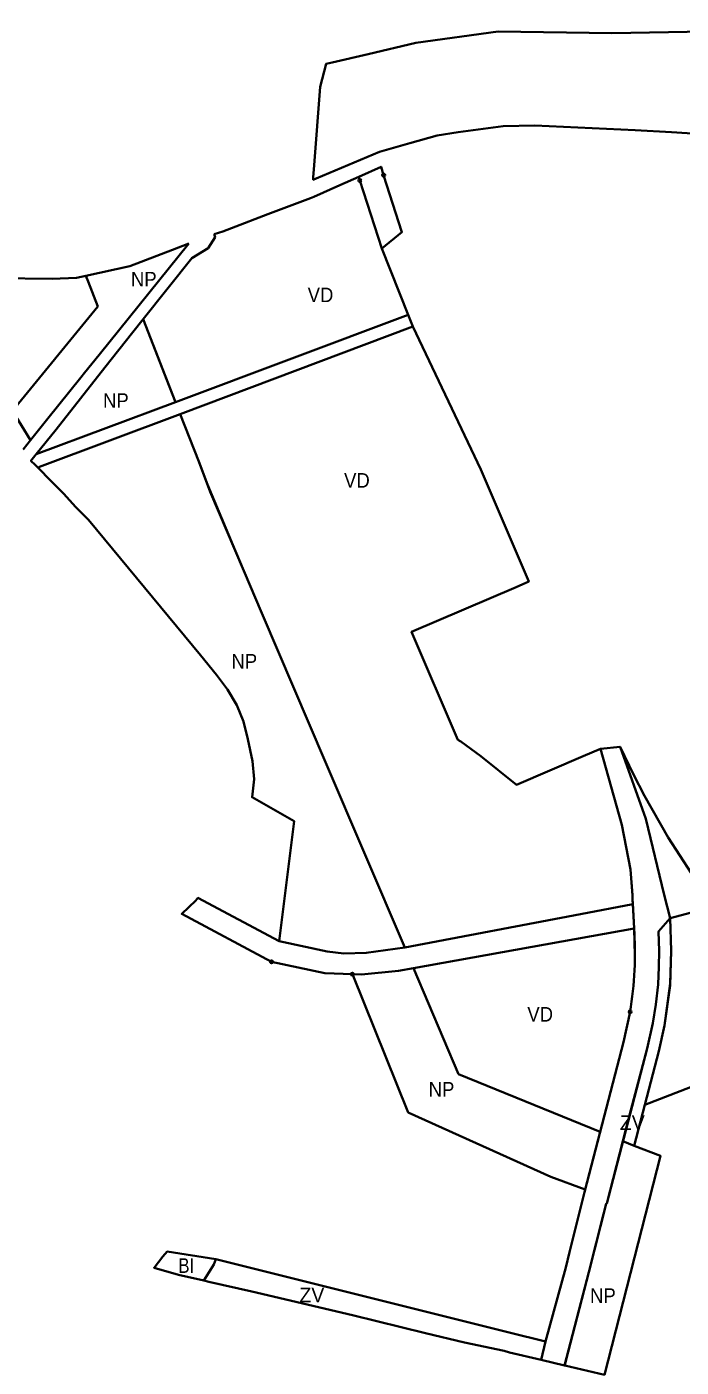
# Model space of a CAD drawing. Extents: x -650276 to -642489, y -1074311 to -1066658.
# Drawn here: x -649558 to -649019, y -1070272 to -1069167 of the extents above; entities that cross this region are included whole.
import ezdxf

# ---------------------------------------------------------------- set-up
doc = ezdxf.new("R2010")
doc.units = 0
doc.header["$LTSCALE"] = 4.8
doc.header["$PDMODE"] = 32
doc.header["$PDSIZE"] = 2.4
for name, color, linetype, lineweight in [('13', 7, 'Continuous', 35), ('15', 7, 'Continuous', 35), ('2', 7, 'Continuous', 35), ('24', 7, 'Continuous', 35), ('35', 7, 'Continuous', 35), ('40', 7, 'Continuous', 35), ('41', 7, 'Continuous', 35), ('48', 7, 'Continuous', 35)]:
    doc.layers.add(name, color=color, linetype=linetype, lineweight=lineweight)
doc.layers.add('62', color=7, linetype='Continuous')

msp = doc.modelspace()

# ---------------------------------------------------------------- linework, layer by layer
at = {"layer": '13'}
msp.add_lwpolyline([(-648800.85, -1069841.52), (-649028.017, -1069902.109), (-649027.135, -1069928.902), (-649027.953, -1069955.702), (-649032.644, -1069990.371), (-649037.411, -1070011.659), (-649048.918, -1070055.852), (-648931.057, -1070010.171)], dxfattribs=at)
at = {"layer": '15'}
msp.add_line((-649057.868, -1069910.51), (-649058.82, -1069890.548), dxfattribs=at)
for points in [[(-649561.17, -1069515.83), (-649555.16, -1069508.07), (-649570.03, -1069483.83), (-649688.625, -1069418.156), (-649755.971, -1069381.179), (-649810.846, -1069362.154), (-649875.434, -1069357.751), (-649934.363, -1069369.537), (-649945.397, -1069375.277), (-649977.239, -1069391.714), (-649994.329, -1069405.451)], [(-649431.761, -1069486.57), (-649240.202, -1069414.528), (-649244.08, -1069404.753), (-649435.578, -1069476.772), (-649550.53, -1069519.68)], [(-649548.881, -1069530.963), (-649547.733, -1069530.185), (-649431.761, -1069486.57)], [(-649550.53, -1069519.68), (-649554.83, -1069525), (-649551.32, -1069528.49), (-649549.69, -1069530.14), (-649548.881, -1069530.963)], [(-649029.61, -1069835.47), (-649049.22, -1069801.23), (-649058.34, -1069783.72), (-649069.4, -1069760.67)], [(-649069.4, -1069760.67), (-649048, -1069820), (-649032.928, -1069882.782)], [(-649032.928, -1069882.782), (-649028.017, -1069902.109), (-648800.85, -1069841.52), (-648806.946, -1069821.79), (-648846.939, -1069832.584), (-648846.94, -1069832.584)], [(-648846.94, -1069832.584), (-648916.03, -1069847.12), (-649010.55, -1069865.09), (-649029.61, -1069835.47)], [(-649417.234, -1069885.193), (-649418.94, -1069887.36), (-649430.515, -1069898.514), (-649356.458, -1069937.945)], [(-649246.81, -1069926.27), (-649278.492, -1069930.573), (-649296.851, -1069931.092), (-649310.738, -1069929.342), (-649350.222, -1069920.873), (-649417.234, -1069885.193)], [(-649058.82, -1069890.548), (-649101.89, -1069898.73), (-649246.81, -1069926.27)], [(-649289.95, -1069948.146), (-649282.437, -1069948.342), (-649251.805, -1069945.276), (-649239.635, -1069943.094), (-649057.868, -1069910.51)], [(-649356.458, -1069937.945), (-649312.646, -1069947.342), (-649289.95, -1069948.146)]]:
    msp.add_lwpolyline(points, dxfattribs=at)
for p in [(-649356.458, -1069937.945), (-649289.95, -1069948.146)]:
    msp.add_point(p, dxfattribs=at)
at = {"layer": '2'}
msp.add_lwpolyline([(-649442.63, -1070176.69), (-649402.29, -1070182.92), (-649404.2, -1070187.43), (-649412.2, -1070200.71), (-649433.3, -1070195.89), (-649453.27, -1070190.02), (-649446.19, -1070180.76)], close=True, dxfattribs=at)
at = {"layer": '24'}
for p, q in [((-649283.702, -1069294.132), (-649265.774, -1069350.068)), ((-649058.858, -1069889.759), (-649057.868, -1069910.51)), ((-649057.134, -1069932.873), (-649057.868, -1069910.51))]:
    msp.add_line(p, q, dxfattribs=at)
for points in [[(-648781.015, -1069167.44), (-649076.02, -1069172.683), (-649169.781, -1069171.432), (-649237.512, -1069180.731), (-649277.021, -1069189.913), (-649306.455, -1069196.754), (-649311.633, -1069197.958), (-649316.47, -1069216.91), (-649321.32, -1069281.47), (-649322.09, -1069291.73), (-649322.22, -1069293.54), (-649319.72, -1069292.47), (-649267.5, -1069270.41), (-649242.5, -1069263.3), (-649220.18, -1069257.03), (-649202.63, -1069254.4), (-649165.62, -1069249.43), (-649139.63, -1069248.73), (-649056.95, -1069252.55), (-649026.955, -1069254.366), (-649001.3, -1069255.92)], [(-649264.156, -1069289.589), (-649266.331, -1069282.804), (-649284.695, -1069291.033), (-649283.702, -1069294.132)], [(-649265.774, -1069350.068), (-649249.069, -1069336.66), (-649264.156, -1069289.589)], [(-649061.138, -1069979.243), (-649061.138, -1069979.243), (-649061.139, -1069979.254), (-649066.487, -1070004.267), (-649098.65, -1070127.795), (-649110.925, -1070177.113), (-649114.174, -1070189.816), (-649130.712, -1070250.935), (-649134.294, -1070266.095), (-649115.159, -1070270.568), (-649095.152, -1070193.731), (-649093.095, -1070186.132), (-649095.152, -1070193.731), (-649080.924, -1070137.409), (-649080.38, -1070136.996), (-649047.131, -1070009.304), (-649042.468, -1069988.477), (-649042.468, -1069988.477), (-649039.966, -1069973.035), (-649037.98, -1069956.626), (-649037.322, -1069942.129), (-649037.137, -1069928.996), (-649037.665, -1069912.977), (-649028.017, -1069902.109), (-649032.928, -1069882.782), (-649048, -1069820), (-649069.4, -1069760.67), (-649085.41, -1069762.44), (-649068, -1069825.147), (-649060.897, -1069861.994)]]:
    msp.add_lwpolyline(points, dxfattribs=at)
for centre, radius, start, end in [((-649633.43, -1069918.001), 575.266, 2.81398, 5.58706), ((-649347.129, -1069931.193), 290, 350.46253, 4.08974), ((-649347.129, -1069931.193), 290, 359.66809, 4.08974)]:
    msp.add_arc(centre, radius, start, end, dxfattribs=at)
for p in [(-649264.156, -1069289.589), (-649283.702, -1069294.132)]:
    msp.add_point(p, dxfattribs=at)
at = {"layer": '35'}
msp.add_line((-649202.375, -1070030.469), (-649085.737, -1070078.201), dxfattribs=at)
for points in [[(-649283.702, -1069294.132), (-649284.695, -1069291.033), (-649300.133, -1069297.95), (-649321.69, -1069307.61)], [(-649244.08, -1069404.753), (-649265.774, -1069350.068), (-649283.702, -1069294.132)], [(-649321.69, -1069307.61), (-649324.3, -1069308.59), (-649359.48, -1069321.82), (-649389.4, -1069333.35), (-649396.52, -1069336.09), (-649403.92, -1069338.26)], [(-649403.92, -1069338.26), (-649403.03, -1069340.66), (-649408.81, -1069349.89), (-649422.19, -1069357.99), (-649462.25, -1069408.32), (-649435.578, -1069476.772), (-649244.08, -1069404.753)], [(-649060.897, -1069861.994), (-649068, -1069825.147), (-649085.41, -1069762.44), (-649085.41, -1069762.44), (-649099.75, -1069768.575), (-649154.76, -1069792.11), (-649184.05, -1069768.45), (-649200.64, -1069756.53), (-649202.99, -1069754.99), (-649241.11, -1069665.9), (-649155.082, -1069629.097), (-649144.57, -1069624.6), (-649184.1, -1069532.2), (-649240.202, -1069414.528), (-649431.761, -1069486.57), (-649416.52, -1069525.68), (-649409.355, -1069544.517), (-649388.438, -1069594.296), (-649379.32, -1069615.71), (-649364.44, -1069650.55), (-649312.03, -1069773.33)], [(-649312.03, -1069773.33), (-649246.81, -1069926.27), (-649101.89, -1069898.73), (-649058.82, -1069890.548)], [(-649057.868, -1069910.51), (-649239.635, -1069943.094), (-649202.375, -1070030.469)], [(-649085.737, -1070078.201), (-649066.487, -1070004.267), (-649061.139, -1069979.254), (-649061.138, -1069979.243)]]:
    msp.add_lwpolyline(points, dxfattribs=at)
for centre, radius, start, end in [((-649649.71, -1069919.176), 591.583, 2.77379, 5.54687), ((-649347.129, -1069931.193), 290, 350.46253, 4.08974)]:
    msp.add_arc(centre, radius, start, end, dxfattribs=at)
msp.add_point((-649061.138, -1069979.243), dxfattribs=at)
at = {"layer": '40'}
for points in [[(-649060.411, -1070060.306), (-649067.061, -1070085.844), (-649057.722, -1070089.665), (-649048.918, -1070055.852), (-649037.411, -1070011.659), (-649032.644, -1069990.371), (-649028.007, -1069957.455), (-649027.135, -1069928.902), (-649028.017, -1069902.109), (-649037.665, -1069912.977), (-649037.137, -1069928.996), (-649037.322, -1069942.129), (-649037.98, -1069956.626), (-649039.966, -1069973.035), (-649042.468, -1069988.477), (-649047.131, -1070009.304)], [(-649160.748, -1070243.413), (-649402.29, -1070182.92), (-649404.2, -1070187.43), (-649412.2, -1070200.71), (-649412.2, -1070200.71), (-649408.24, -1070201.62), (-649372.69, -1070209.74), (-649289.83, -1070229.16), (-649229.8, -1070243.94), (-649197.55, -1070251.65), (-649164.91, -1070258.55), (-649160.54, -1070259.96), (-649134.294, -1070266.095), (-649130.712, -1070250.935)]]:
    msp.add_lwpolyline(points, close=True, dxfattribs=at)
at = {"layer": '41'}
msp.add_lwpolyline([(-649570.03, -1069483.83), (-649499.761, -1069397.905), (-649507.61, -1069377.35), (-649509.42, -1069372.61), (-649517.17, -1069374.3), (-649537.32, -1069375.23), (-649582.25, -1069374.51)], dxfattribs=at)
at = {"layer": '48'}
for points in [[(-649555.16, -1069508.07), (-649540.81, -1069490.25), (-649513.66, -1069456.53), (-649510.56, -1069452.67), (-649498.47, -1069437.65), (-649424.8, -1069346.14)], [(-649424.8, -1069346.14), (-649438.17, -1069351.27), (-649473.35, -1069364.76), (-649473.35, -1069364.76), (-649509.42, -1069372.61), (-649507.61, -1069377.35), (-649499.761, -1069397.905)], [(-649499.761, -1069397.905), (-649570.03, -1069483.83), (-649555.16, -1069508.07)], [(-649493.94, -1069448.14), (-649534.06, -1069499.33), (-649550.53, -1069519.68), (-649435.578, -1069476.772), (-649440.466, -1069464.229), (-649462.25, -1069408.32)], [(-649462.25, -1069408.32), (-649470.71, -1069418.95), (-649493.94, -1069448.14), (-649493.94, -1069448.14)], [(-649114.172, -1070266.777), (-649114.931, -1070270.621), (-649082.233, -1070278.265), (-649036.031, -1070097.854), (-649057.722, -1070089.665), (-649067.061, -1070085.844)], [(-649067.061, -1070085.844), (-649080.38, -1070136.996), (-649080.872, -1070137.369), (-649083.108, -1070146.053)], [(-649083.108, -1070146.053), (-649095.152, -1070193.731), (-649093.095, -1070186.132), (-649095.152, -1070193.731), (-649114.172, -1070266.777)]]:
    msp.add_lwpolyline(points, dxfattribs=at)
for points in [[(-649392.85, -1069713.53), (-649385.25, -1069726.48), (-649379.49, -1069740.04), (-649376.01, -1069754.58), (-649372.2, -1069772.58), (-649370.94, -1069787.45), (-649372.56, -1069802.33), (-649372.56, -1069802.33), (-649338, -1069822), (-649350.222, -1069920.873), (-649310.738, -1069929.342), (-649296.851, -1069931.092), (-649278.492, -1069930.573), (-649246.81, -1069926.27), (-649312.03, -1069773.33), (-649364.44, -1069650.55), (-649379.32, -1069615.71), (-649407.002, -1069550.701), (-649416.52, -1069525.68), (-649431.761, -1069486.57), (-649547.733, -1069530.185), (-649548.881, -1069530.963), (-649538.49, -1069541.54), (-649527.84, -1069552.16), (-649517.81, -1069563.27), (-649507.23, -1069573.85), (-649474.46, -1069613.59), (-649415.12, -1069685.26), (-649401.77, -1069701.47)], [(-649251.805, -1069945.276), (-649282.437, -1069948.342), (-649289.95, -1069948.146), (-649243.846, -1070062.071), (-649126.437, -1070115.217), (-649126.437, -1070115.217), (-649098.101, -1070125.688), (-649085.737, -1070078.201), (-649202.375, -1070030.469), (-649239.635, -1069943.094)]]:
    msp.add_lwpolyline(points, close=True, dxfattribs=at)

# ---------------------------------------------------------------- texts
at = {"layer": '62'}
for s, width, p in [('NP', 0.95, (-649472.389, -1069381.42)), ('VD', 0.95, (-649326.761, -1069394.352)), ('NP', 0.95, (-649495.389, -1069481.42)), ('VD', 0.95, (-649296.767, -1069547.204)), ('NP', 0.95, (-649389.556, -1069696.287)), ('VD', 0.95, (-649145.767, -1069987.204)), ('NP', 0.95, (-649227.076, -1070049.026)), ('BI', 0.85, (-649433.221, -1070194.292)), ('NP', 0.95, (-649094.076, -1070219.026))]:
    msp.add_text(s, height=12, dxfattribs=dict(at, width=width)).set_placement(p)
for p in [(-649069.527, -1070076.528), (-649333.527, -1070218.528)]:
    msp.add_text('ZV', height=12, dxfattribs=at).set_placement(p)

doc.saveas('drawing.dxf')
